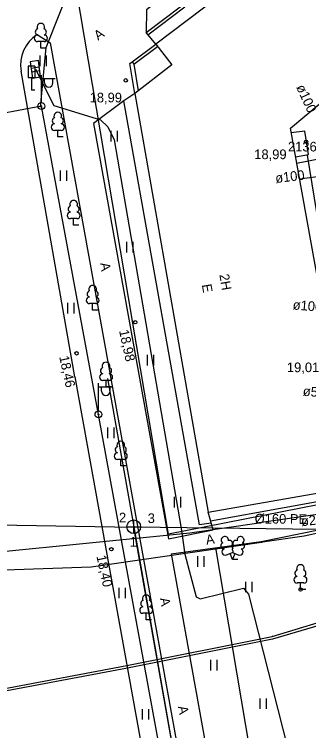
# Model space of a CAD drawing. Extents: x 713497 to 713863, y 6590062 to 6590327.
# Drawn here: x 713647.4 to 713668.7, y 6590142.1 to 6590194 of the extents above; entities that cross this region are included whole.
import ezdxf

# ---------------------------------------------------------------- set-up
doc = ezdxf.new("R2010")
doc.units = 0
for name, color, linetype in [('AED', 7, 'Continuous'), ('HALJASTUS', 7, 'Continuous'), ('HOONE', 7, 'Continuous'), ('HOONEDET', 7, 'Continuous'), ('KKAEV', 7, 'Continuous'), ('KORGUS', 7, 'Continuous'), ('KTRASS', 7, 'Continuous'), ('LIIKLUS', 7, 'Continuous'), ('MPKAABEL', 7, 'Continuous'), ('POST', 7, 'Continuous'), ('PUU', 7, 'Continuous'), ('SIKAEV', 7, 'Continuous'), ('SITRASS', 7, 'Continuous'), ('TEE', 7, 'Continuous'), ('TORU NR', 7, 'Continuous'), ('Слой 1', 7, 'Continuous')]:
    doc.layers.add(name, color=color, linetype=linetype)

msp = doc.modelspace()

# ---------------------------------------------------------------- linework, layer by layer
at = {"layer": 'AED'}
msp.add_lwpolyline([(713666.634, 6590127.751), (713661.97, 6590155.352)], dxfattribs=at)
at = {"layer": 'HALJASTUS'}
for p, q in [((713649.226, 6590190.995), (713649.226, 6590190.234)), ((713649.681, 6590190.995), (713649.681, 6590190.234)), ((713654.358, 6590185.544), (713654.358, 6590184.783)), ((713654.813, 6590185.544), (713654.813, 6590184.783)), ((713650.701, 6590182.677), (713650.701, 6590181.915)), ((713651.156, 6590182.677), (713651.156, 6590181.915)), ((713655.508, 6590177.499), (713655.508, 6590176.738)), ((713655.963, 6590177.499), (713655.963, 6590176.738)), ((713651.227, 6590173.082), (713651.227, 6590172.321)), ((713651.682, 6590173.082), (713651.682, 6590172.321)), ((713657.003, 6590169.319), (713657.003, 6590168.558)), ((713657.458, 6590169.319), (713657.458, 6590168.558)), ((713654.116, 6590164.047), (713654.116, 6590163.286)), ((713654.571, 6590164.047), (713654.571, 6590163.286)), ((713658.958, 6590159.032), (713658.958, 6590158.271)), ((713659.413, 6590159.032), (713659.413, 6590158.271)), ((713660.639, 6590154.731), (713660.639, 6590153.97)), ((713661.094, 6590154.731), (713661.094, 6590153.97)), ((713664.116, 6590152.887), (713664.116, 6590152.126)), ((713664.571, 6590152.887), (713664.571, 6590152.126)), ((713654.949, 6590152.446), (713654.949, 6590151.685)), ((713655.404, 6590152.446), (713655.404, 6590151.685)), ((713661.583, 6590147.224), (713661.583, 6590146.463)), ((713662.039, 6590147.224), (713662.039, 6590146.463)), ((713665.146, 6590144.436), (713665.146, 6590143.674)), ((713665.601, 6590144.436), (713665.601, 6590143.674)), ((713656.641, 6590143.663), (713656.641, 6590142.902)), ((713657.096, 6590143.663), (713657.096, 6590142.902))]:
    msp.add_line(p, q, dxfattribs=at)
at = {"layer": 'HOONE'}
msp.add_lwpolyline([(713694.46, 6590176.83), (713699.344, 6590186.554), (713671.45, 6590200.16), (713668.812, 6590198.114), (713667.734, 6590199.504), (713663.207, 6590196.061), (713662.943, 6590196.409), (713661.91, 6590195.607), (713662.167, 6590195.27), (713657.62, 6590191.813), (713658.772, 6590190.327), (713656.103, 6590188.256), (713661.399, 6590157.924), (713672.043, 6590159.781), (713667.37, 6590185.73), (713670.62, 6590188.46), (713694.46, 6590176.83)], dxfattribs=at)
at = {"layer": 'HOONEDET'}
for p, q in [((713657.049, 6590192.502), (713659.726, 6590194.537)), ((713656.017, 6590190.385), (713657.742, 6590191.655)), ((713655.898, 6590190.546), (713656.017, 6590190.385)), ((713656.017, 6590190.385), (713656.34, 6590188.44))]:
    msp.add_line(p, q, dxfattribs=at)
for points in [[(713656.103, 6590188.256), (713655.742, 6590190.431), (713655.898, 6590190.546), (713657.62, 6590191.813), (713656.921, 6590192.656), (713659.489, 6590194.608)], [(713667.73, 6590183.65), (713668.68, 6590183.82), (713668.42, 6590185.51), (713667.43, 6590185.4)], [(713670.93, 6590169.53), (713668.6, 6590183.79)], [(713661.59, 6590157.309), (713672.24, 6590159.22), (713672.82, 6590159.27), (713671.41, 6590167.74)]]:
    msp.add_lwpolyline(points, dxfattribs=at)
at = {"layer": 'KKAEV'}
for p, q in [((713656.018, 6590156.368), (713656.018, 6590157.368)), ((713655.518, 6590156.868), (713656.518, 6590156.868))]:
    msp.add_line(p, q, dxfattribs=at)
msp.add_circle((713656.018, 6590156.868), 0.5, dxfattribs=at)
at = {"layer": 'KORGUS'}
for centre in [(713655.44, 6590189.2), (713668.5, 6590184.75), (713656.13, 6590171.68), (713651.88, 6590169.43), (713654.4, 6590155.24), (713668.1, 6590152.32)]:
    msp.add_circle(centre, 0.125, dxfattribs=at)
at = {"layer": 'KTRASS'}
for p, q in [((713656.03, 6590156.825), (713639.892, 6590157.082)), ((713662.007, 6590123.147), (713656.03, 6590156.825))]:
    msp.add_line(p, q, dxfattribs=at)
for points in [[(713671.737, 6590182.535), (713668.022, 6590182.04)], [(713654.124, 6590167.604), (713656.018, 6590156.868)], [(713656.018, 6590156.868), (713675.202, 6590156.629)], [(713656.018, 6590156.868), (713659.344, 6590138.013)]]:
    msp.add_lwpolyline(points, dxfattribs=at)
at = {"layer": 'LIIKLUS'}
for points in [[(713648.364, 6590190.233), (713648.364, 6590189.383)], [(713648.864, 6590190.233), (713648.364, 6590190.233)], [(713648.864, 6590190.233), (713648.864, 6590189.383)], [(713648.864, 6590189.383), (713648.364, 6590189.383)], [(713648.614, 6590189.383), (713648.614, 6590188.483)], [(713648.864, 6590188.483), (713648.614, 6590188.483)]]:
    msp.add_lwpolyline(points, dxfattribs=at)
at = {"layer": 'MPKAABEL'}
for points in [[(713649.332, 6590187.338), (713640.094, 6590185.585), (713635.77, 6590206.95), (713632.04, 6590224.25), (713630.57, 6590226.81), (713628.65, 6590228.67), (713627.42, 6590229.49), (713598.73, 6590243.21), (713583.058, 6590248.245), (713565.046, 6590256.189), (713523.612, 6590274.149), (713521.905, 6590274.877)], [(713649.277, 6590187.265), (713649.689, 6590191.57), (713651.67, 6590196.573), (713666.461, 6590208.741), (713673.579, 6590208.987)], [(713648.898, 6590189.999), (713650.232, 6590187.386), (713653.619, 6590186.331), (713654.135, 6590185.833), (713654.6, 6590184.884), (713659.445, 6590156.75), (713659.718, 6590154.881), (713660.539, 6590151.792), (713660.839, 6590151.655), (713663.967, 6590152.428), (713664.337, 6590151.977), (713669.307, 6590132.418), (713669.804, 6590132.227), (713691.237, 6590138.869), (713696.964, 6590141.27), (713697.553, 6590141.309), (713698.727, 6590140.465), (713701.978, 6590137.747), (713706.02, 6590136.037), (713711.684, 6590136.564)], [(713659.555, 6590131.794), (713653.466, 6590165.007), (713649.332, 6590187.338)], [(713695.67, 6590069.59), (713692.27, 6590087.9), (713686.34, 6590118.33), (713684.33, 6590125.92), (713682.83, 6590130.66), (713676.1, 6590152.02), (713674.73, 6590155.85), (713674.34, 6590157.36), (713673.46, 6590161.22), (713670.72, 6590177.53), (713669.67, 6590183.54), (713667.81, 6590183.17)], [(713628.364, 6590166.869), (713632.08, 6590167.48), (713633.015, 6590162.313), (713634.41, 6590159.02), (713637.59, 6590156.404), (713640.542, 6590143.998), (713655.527, 6590146.824), (713666.053, 6590148.923), (713666.104, 6590148.937), (713666.053, 6590148.923), (713676.52, 6590152.11), (713677.82, 6590153.38), (713679.31, 6590155.11), (713679.81, 6590159.44), (713679.75, 6590161.04), (713679.53, 6590162.08), (713679.1, 6590163.05), (713677.79, 6590165.07), (713675.3, 6590167.39), (713673.09, 6590169.87), (713671.63, 6590170.7), (713670.72, 6590170.92), (713670.037, 6590170.92)], [(713712.95, 6590130.05), (713709.16, 6590129.42), (713701.69, 6590129.47), (713690.5, 6590129.51), (713688.19, 6590129.12), (713683.66, 6590141.1), (713679.81, 6590148.4), (713679.37, 6590149.39), (713679.04, 6590150.26), (713678.83, 6590150.79), (713678.48, 6590151.44), (713677.98, 6590152.02), (713677.43, 6590152.31), (713676.95, 6590152.28), (713676.524, 6590152.014), (713670.183, 6590149.934), (713666.077, 6590148.723), (713655.565, 6590146.628), (713640.392, 6590143.766), (713637.411, 6590156.292), (713634.246, 6590158.892), (713632.822, 6590162.256), (713631.92, 6590167.25), (713628.288, 6590166.652)], [(713674.28, 6590157.49), (713668.35, 6590156.18), (713665.344, 6590155.743), (713665.26, 6590155.731), (713652.94, 6590153.94), (713637.63, 6590153.4), (713630.492, 6590152.158)]]:
    msp.add_lwpolyline(points, dxfattribs=at)
at = {"layer": 'POST'}
for p, q in [((713649.115, 6590190.631), (713648.523, 6590190.552)), ((713648.523, 6590190.552), (713648.681, 6590189.368)), ((713649.273, 6590189.446), (713649.115, 6590190.631)), ((713648.584, 6590190.094), (713649.176, 6590190.173)), ((713648.62, 6590189.825), (713649.212, 6590189.904)), ((713648.681, 6590189.368), (713649.273, 6590189.446)), ((713649.332, 6590187.588), (713649.332, 6590189.588)), ((713649.332, 6590189.338), (713650.332, 6590189.338)), ((713649.558, 6590189.018), (713649.558, 6590189.338)), ((713650.171, 6590189.018), (713650.171, 6590189.338)), ((713653.466, 6590165.257), (713653.466, 6590167.257)), ((713653.466, 6590167.007), (713654.466, 6590167.007)), ((713653.693, 6590166.686), (713653.693, 6590167.007)), ((713654.305, 6590166.686), (713654.305, 6590167.007))]:
    msp.add_line(p, q, dxfattribs=at)
for centre, radius in [((713649.332, 6590187.338), 0.25), ((713649.332, 6590187.338), 0.0234), ((713653.466, 6590165.007), 0.25), ((713653.466, 6590165.007), 0.0234)]:
    msp.add_circle(centre, radius, dxfattribs=at)
for centre in [(713649.865, 6590189.018), (713653.999, 6590166.686)]:
    msp.add_arc(centre, 0.306, 180, 0, dxfattribs=at)
at = {"layer": 'PUU'}
for p, q in [((713649.534, 6590192.007), (713649.054, 6590192.007)), ((713649.294, 6590191.532), (713649.294, 6590192.007)), ((713649.674, 6590191.532), (713649.294, 6590191.532)), ((713650.76, 6590185.574), (713650.28, 6590185.574)), ((713650.52, 6590185.099), (713650.52, 6590185.574)), ((713650.9, 6590185.099), (713650.52, 6590185.099)), ((713651.91, 6590179.184), (713651.43, 6590179.184)), ((713651.67, 6590178.709), (713651.67, 6590179.184)), ((713652.05, 6590178.709), (713651.67, 6590178.709)), ((713653.285, 6590173.029), (713652.805, 6590173.029)), ((713653.045, 6590172.554), (713653.045, 6590173.029)), ((713653.425, 6590172.554), (713653.045, 6590172.554)), ((713654.254, 6590167.47), (713653.774, 6590167.47)), ((713654.014, 6590166.995), (713654.014, 6590167.47)), ((713654.394, 6590166.995), (713654.014, 6590166.995)), ((713655.32, 6590161.744), (713654.84, 6590161.744)), ((713655.08, 6590161.269), (713655.08, 6590161.744)), ((713655.46, 6590161.269), (713655.08, 6590161.269)), ((713662.734, 6590154.827), (713663.179, 6590155.002)), ((713663.174, 6590154.492), (713662.999, 6590154.932)), ((713663.174, 6590154.492), (713663.354, 6590154.932)), ((713663.179, 6590155.002), (713663.619, 6590154.822)), ((713663.554, 6590154.492), (713663.174, 6590154.492)), ((713668.33, 6590152.795), (713667.85, 6590152.795)), ((713668.09, 6590152.32), (713668.09, 6590152.795)), ((713668.47, 6590152.32), (713668.09, 6590152.32)), ((713657.166, 6590150.598), (713656.686, 6590150.598)), ((713656.926, 6590150.123), (713656.926, 6590150.598)), ((713657.306, 6590150.123), (713656.926, 6590150.123))]:
    msp.add_line(p, q, dxfattribs=at)
msp.add_lwpolyline([(713663.179, 6590155.497), (713663.159, 6590155.422), (713663.159, 6590155.402), (713663.169, 6590155.372), (713663.189, 6590155.337), (713663.194, 6590155.317), (713663.179, 6590155.282), (713663.154, 6590155.232), (713663.149, 6590155.207), (713663.154, 6590155.192), (713663.164, 6590155.162), (713663.199, 6590155.102), (713663.204, 6590155.082), (713663.199, 6590155.062), (713663.184, 6590155.027), (713663.179, 6590155.002)], dxfattribs=at)
for centre, radius, start, end in [((713649.294, 6590193.052), 0.277, 332.5799, 207.4201), ((713649.056, 6590192.245), 0.238, 90.0016, 269.3953), ((713649.124, 6590192.705), 0.233, 109.0217, 253.1415), ((713649.464, 6590192.705), 0.233, 286.8508, 70.9859), ((713649.531, 6590192.245), 0.238, 270.6047, 89.9984), ((713650.52, 6590186.619), 0.277, 332.5799, 207.4201), ((713650.35, 6590186.271), 0.233, 109.0217, 253.1415), ((713650.69, 6590186.271), 0.233, 286.8508, 70.9859), ((713650.283, 6590185.811), 0.238, 90.0016, 269.3953), ((713650.758, 6590185.811), 0.238, 270.6047, 89.9984), ((713651.5, 6590179.881), 0.233, 109.0217, 253.1415), ((713651.67, 6590180.229), 0.277, 332.5799, 207.4201), ((713651.84, 6590179.881), 0.233, 286.8508, 70.9859), ((713651.432, 6590179.421), 0.238, 90.0016, 269.3953), ((713651.907, 6590179.421), 0.238, 270.6047, 89.9984), ((713653.045, 6590174.074), 0.277, 332.5799, 207.4201), ((713652.875, 6590173.726), 0.233, 109.0217, 253.1415), ((713653.215, 6590173.726), 0.233, 286.8508, 70.9859), ((713652.808, 6590173.266), 0.238, 90.0016, 269.3953), ((713653.283, 6590173.266), 0.238, 270.6047, 89.9984), ((713654.014, 6590168.515), 0.277, 332.5799, 207.4201), ((713653.844, 6590168.168), 0.233, 109.0217, 253.1415), ((713654.184, 6590168.168), 0.233, 286.8508, 70.9859), ((713653.777, 6590167.707), 0.238, 90.0016, 269.3953), ((713654.252, 6590167.707), 0.238, 270.6047, 89.9984), ((713655.08, 6590162.789), 0.277, 332.5799, 207.4201), ((713654.91, 6590162.441), 0.233, 109.0217, 253.1415), ((713655.25, 6590162.441), 0.233, 286.8508, 70.9859), ((713654.843, 6590161.981), 0.238, 90.0016, 269.3953), ((713655.318, 6590161.981), 0.238, 270.6047, 89.9984), ((713662.616, 6590155.906), 0.256, 350.4856, 111.5002), ((713663.752, 6590155.898), 0.256, 67.6168, 188.6314), ((713662.543, 6590155.495), 0.224, 111.4304, 274.4987), ((713662.616, 6590155.906), 0.256, 111.5027, 232.5173), ((713662.951, 6590155.656), 0.224, 308.5041, 111.5725), ((713663.414, 6590155.651), 0.225, 67.7016, 230.5126), ((713663.82, 6590155.485), 0.224, 264.6183, 67.6866), ((713663.752, 6590155.898), 0.256, 306.5997, 67.6143), ((713662.647, 6590155.051), 0.237, 111.5014, 291.5004), ((713663.178, 6590155.26), 0.237, 66.7655, 111.5015), ((713663.708, 6590155.043), 0.237, 247.6166, 67.6155), ((713668.09, 6590153.84), 0.277, 332.5799, 207.4201), ((713667.92, 6590153.493), 0.233, 109.0217, 253.1415), ((713668.26, 6590153.493), 0.233, 286.8508, 70.9859), ((713667.853, 6590153.032), 0.238, 90.0016, 269.3953), ((713668.327, 6590153.032), 0.238, 270.6047, 89.9984), ((713656.756, 6590151.296), 0.233, 109.0217, 253.1415), ((713656.926, 6590151.643), 0.277, 332.5799, 207.4201), ((713657.096, 6590151.296), 0.233, 286.8508, 70.9859), ((713656.688, 6590150.836), 0.238, 90.0016, 269.3953), ((713657.163, 6590150.836), 0.238, 270.6047, 89.9984)]:
    msp.add_arc(centre, radius, start, end, dxfattribs=at)
at = {"layer": 'SITRASS'}
for points in [[(713631.121, 6590185.897), (713633.455, 6590186.339), (713638.75, 6590154.309), (713660.08, 6590156.42), (713665.095, 6590157.143)], [(713675.61, 6590158.66), (713665.094, 6590157.143)]]:
    msp.add_lwpolyline(points, dxfattribs=at)
at = {"layer": 'TEE'}
for points in [[(713659.37, 6590196.194), (713656.941, 6590194.319), (713656.921, 6590192.656)], [(713649.03, 6590192.526), (713649.958, 6590191.922), (713661.582, 6590127.66)], [(713651.761, 6590167.73), (713647.86, 6590189.859)], [(713656.103, 6590188.256), (713655.296, 6590187.711), (713653.106, 6590186.076)], [(713661.636, 6590157.119), (713660.791, 6590157.005), (713655.296, 6590187.711)], [(713653.106, 6590186.076), (713658.542, 6590156.003), (713661.777, 6590156.64), (713661.399, 6590157.924)], [(713658.74, 6590154.907), (713665.251, 6590155.804), (713675.21, 6590157.83), (713676.19, 6590158.5), (713681.26, 6590161.94), (713685.06, 6590164.53), (713690.28, 6590168), (713694.82, 6590170.96), (713697.09, 6590172.81), (713697.433, 6590173.143)], [(713651.761, 6590167.73), (713658.736, 6590129.062)], [(713658.74, 6590154.907), (713663.747, 6590127.042)]]:
    msp.add_lwpolyline(points, dxfattribs=at)
msp.add_arc((713650.445, 6590190.315), 2.625, 122.624, 189.9989, dxfattribs=at)
at = {"layer": 'Слой 1'}
msp.add_lwpolyline([(713703.47, 6590188.07), (713697.32, 6590175.48), (713675.01, 6590159.57), (713658.54, 6590156.33), (713651.88, 6590195.77), (713668, 6590206.8)], close=True, dxfattribs=at)

# ---------------------------------------------------------------- texts
at = {"layer": 'HOONE'}
for s, p in [('2H', (713662.217, 6590175.127)), ('E', (713660.947, 6590174.393))]:
    msp.add_text(s, height=0.7, rotation=279.6065, dxfattribs=at).set_placement(p)
at = {"layer": 'KORGUS'}
for s, p in [('18,99', (713652.826, 6590187.605)), ('18,99', (713664.746, 6590183.495)), ('19,01', (713667.112, 6590168.065))]:
    msp.add_text(s, height=0.7, dxfattribs=at).set_placement(p)
for s, p in [('18,98', (713654.952, 6590171.067)), ('18,46', (713650.616, 6590169.188)), ('18,40', (713653.312, 6590154.737))]:
    msp.add_text(s, height=0.7, rotation=282.3666, dxfattribs=at).set_placement(p)
at = {"layer": 'KTRASS'}
msp.add_text('%%c160 PE', height=0.7, rotation=359.4787, dxfattribs=at).set_placement((713664.774, 6590157.11))
at = {"layer": 'SIKAEV'}
msp.add_text('2136', height=0.7, dxfattribs=at).set_placement((713667.19, 6590184.05))
at = {"layer": 'TEE'}
for rotation, p in [(35.2034, (713653.441, 6590192.068)), (279.311, (713653.587, 6590175.954)), (8.9678, (713661.292, 6590155.568)), (279.7522, (713657.913, 6590151.679)), (280.6754, (713659.219, 6590143.836))]:
    msp.add_text('A', height=0.7, rotation=rotation, dxfattribs=at).set_placement(p)
at = {"layer": 'TORU NR'}
for s, rotation, p in [('ø100', 294.5451, (713667.767, 6590188.715)), ('ø100', 6.9743, (713666.307, 6590181.758)), ('ø100', 355.3621, (713667.511, 6590172.609)), ('ø56', 355.3621, (713668.238, 6590166.358)), ('ø200', 6.0077, (713668.167, 6590156.906))]:
    msp.add_text(s, height=0.7, rotation=rotation, dxfattribs=at).set_placement(p)
for s, p in [('2', (713654.952, 6590157.184)), ('3', (713657.03, 6590157.139)), ('1', (713655.726, 6590155.425))]:
    msp.add_text(s, height=0.7, dxfattribs=at).set_placement(p)

doc.saveas('drawing.dxf')
